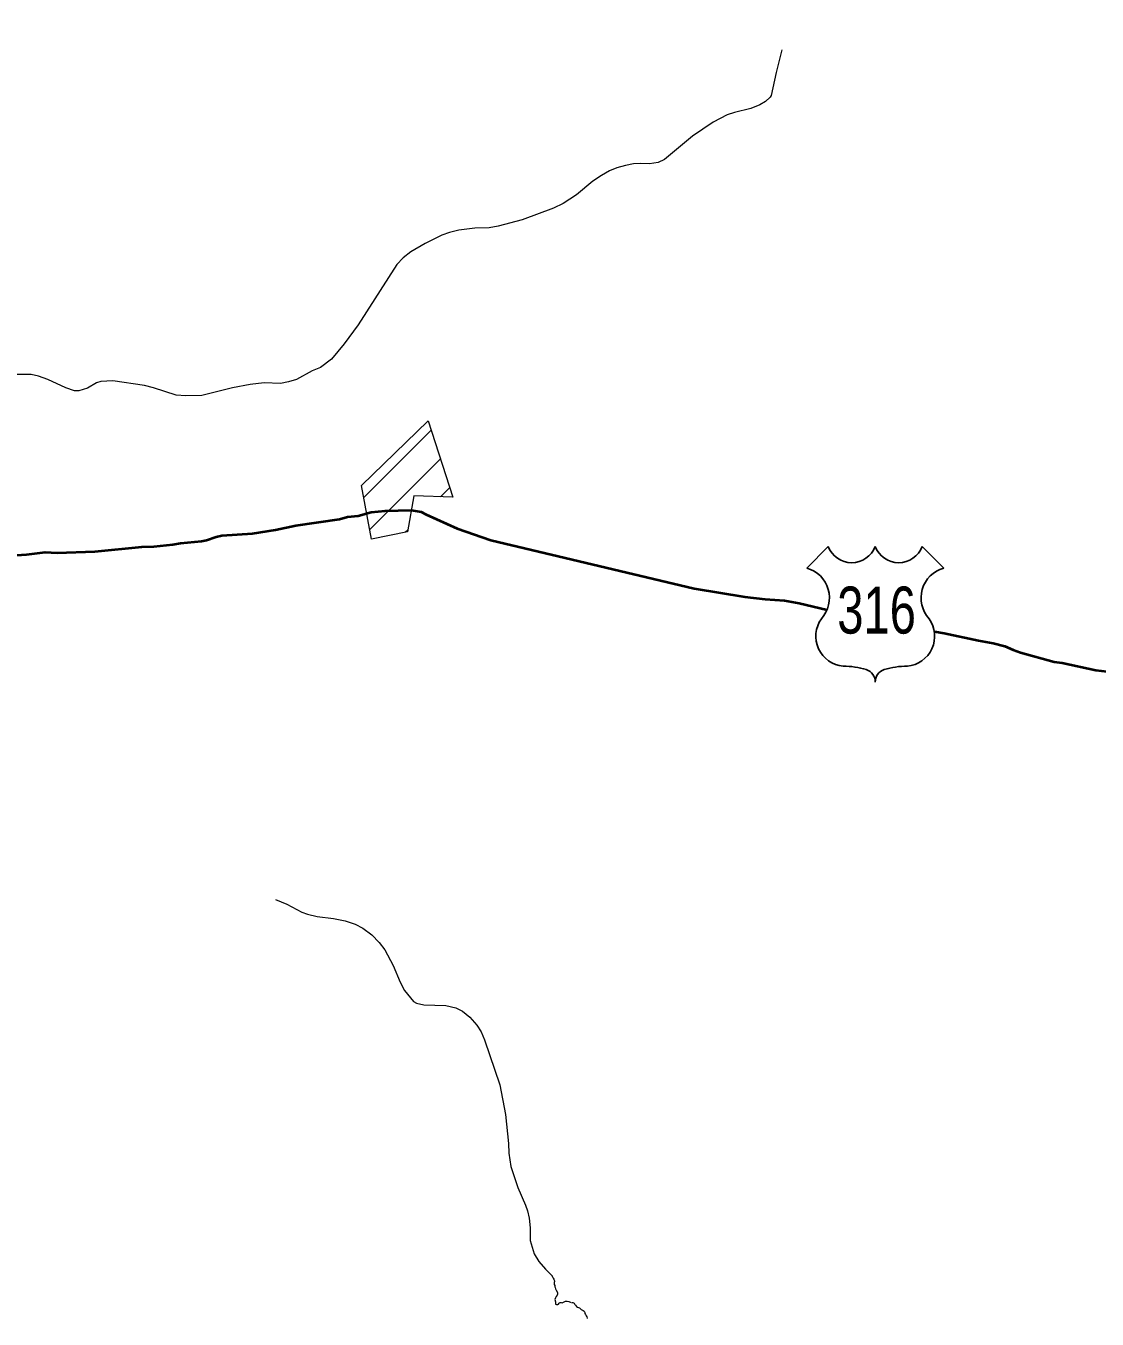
# Model space of a CAD drawing. Extents: x -1643653 to 4543381, y 1624270 to 13878484.
# Drawn here: x 612033 to 613629, y 8911161 to 8913088 of the extents above; entities that cross this region are included whole.
import ezdxf
from ezdxf.enums import TextEntityAlignment as Align

# ---------------------------------------------------------------- set-up
doc = ezdxf.new("R2010")
doc.units = 0
doc.header["$LTSCALE"] = 160
doc.layers.add('6', color=7, linetype='Continuous', lineweight=13)
doc.layers.add('60', color=7, linetype='Continuous', lineweight=13)

msp = doc.modelspace()

# ---------------------------------------------------------------- linework, layer by layer
at = {"layer": '6'}
for p, q in [((612536.6, 8912385.5), (612637.1, 8912486)), ((612545.6, 8912337.9), (612650.9, 8912443.2)), ((612651.1, 8912386.8), (612664.7, 8912400.5)), ((612598.1, 8912333.9), (612602.5, 8912338.2))]:
    msp.add_line(p, q, dxfattribs=at)
at = {"layer": '6', "lineweight": 25}
for p, q in [((613196.5, 8912280.5), (613228.5, 8912312.5)), ((613368.3, 8912312.5), (613400.3, 8912280.5))]:
    msp.add_line(p, q, dxfattribs=at)
at = {"layer": '6'}
for points in [[(613159.1, 8913052.5), (613150.7, 8913018.9), (613143.3, 8912984.7), (613141.8, 8912982.2), (613135, 8912975.7), (613126.6, 8912970.5), (613113.2, 8912965.1), (613088.7, 8912959.4), (613077.6, 8912955.9), (613056.8, 8912945.1), (613026.4, 8912924.2), (612984.3, 8912889.5), (612975.3, 8912885), (612962, 8912882.7), (612949.3, 8912883.3), (612938.2, 8912882.9), (612926.3, 8912880.4), (612913.6, 8912876.7), (612902.5, 8912872.2), (612890.6, 8912865.5), (612878, 8912856.9), (612853.6, 8912836.8), (612833.4, 8912823.5), (612819.3, 8912816.9), (612772.4, 8912799.4), (612736.7, 8912790.1), (612723.2, 8912787.6), (612701.8, 8912787.2), (612678, 8912783.9), (612664.5, 8912780.4), (612652.7, 8912776.3), (612628.1, 8912764), (612606.6, 8912751.9), (612595.2, 8912743), (612585.7, 8912732.6), (612528.2, 8912642.8), (612507.4, 8912614.5), (612488.7, 8912591.9), (612472.2, 8912579.6), (612459.6, 8912574.3), (612436.4, 8912561.7), (612424.6, 8912558.2), (612412.7, 8912555.7), (612388.1, 8912556.3), (612367.4, 8912554.2), (612341.2, 8912549.2), (612295.2, 8912537.7), (612271.4, 8912536.9), (612257.2, 8912538.1), (612223.7, 8912549.1), (612210.3, 8912552.6), (612162.7, 8912559.7), (612144.9, 8912558.7), (612138.8, 8912556.3), (612125.4, 8912548.8), (612112.3, 8912544.7), (612106, 8912544.6), (612092.8, 8912549.1), (612065.9, 8912561.3), (612052.4, 8912566.6), (612041.2, 8912568.8), (612020.6, 8912568.7)], [(612405.4, 8911786.9), (612421.9, 8911779.7), (612444.2, 8911767.9), (612452.9, 8911764.7), (612467, 8911761.3), (612491.4, 8911758.4), (612508.9, 8911754.9), (612524, 8911749.8), (612535, 8911743.9), (612548.6, 8911733.8), (612559.7, 8911722.7), (612568.1, 8911711.9), (612580.6, 8911688.2), (612590.9, 8911663.6), (612597.2, 8911651.2), (612610.8, 8911634.7), (612615.1, 8911632.4), (612626.2, 8911629.9), (612658.6, 8911628.8), (612673.5, 8911625.1), (612683.9, 8911620.1), (612694.8, 8911611.3), (612705, 8911599.6), (612711.5, 8911589.3), (612716.3, 8911577.6), (612739.5, 8911510.5), (612747.7, 8911466.3), (612752.2, 8911422.9), (612752.6, 8911408.8), (612755.4, 8911389), (612765.9, 8911357.3), (612777.4, 8911331.4), (612780.4, 8911322.6), (612782.9, 8911311.6), (612784.4, 8911297.5), (612784.2, 8911278.4), (612790.5, 8911258.6), (612797.4, 8911247.3), (612807.2, 8911235.8), (612817.1, 8911225.9)], [(612817.1, 8911225.9), (612817.4, 8911225), (612818, 8911223.9), (612818.6, 8911222.4), (612819.6, 8911220.8), (612820.4, 8911219.5), (612820.6, 8911218.7), (612820.6, 8911217.4), (612820.3, 8911215.9), (612820.2, 8911213.9), (612820.4, 8911213), (612821.1, 8911211.6), (612821.3, 8911210.5), (612821, 8911209.4)], [(612821, 8911209.4), (612821.6, 8911208.3), (612822.4, 8911206.7), (612823.2, 8911204.4), (612824.9, 8911200.9), (612825.3, 8911199.8), (612825.2, 8911198.6), (612824.6, 8911197.1), (612823.1, 8911195.1), (612822, 8911193.1), (612821.4, 8911190.8), (612822.3, 8911187), (612822.3, 8911184.5), (612822.3, 8911183.5)], [(612822.3, 8911183.6), (612823.9, 8911183.1), (612824.8, 8911183), (612825.5, 8911183.1), (612826.4, 8911183.6), (612827.5, 8911185), (612828.1, 8911185.7), (612829, 8911186), (612830.5, 8911186), (612832.3, 8911185.9), (612834.3, 8911186.6), (612835.2, 8911187), (612837.1, 8911188), (612838.2, 8911188.2), (612839.3, 8911188), (612841.9, 8911187.6), (612843.1, 8911187.2), (612844.3, 8911186.8), (612845.2, 8911186.6)], [(612845.8, 8911186.4), (612847.8, 8911186.2), (612848.8, 8911185.9), (612850.1, 8911185.3), (612851.1, 8911183.4), (612851.8, 8911182.1), (612853.2, 8911180.4), (612854.8, 8911179.4), (612856.6, 8911178.8), (612858, 8911178), (612859.3, 8911176.8), (612860.2, 8911175.8), (612861.6, 8911175.2), (612863.6, 8911174.4), (612864.9, 8911173.1), (612865.7, 8911171.2), (612866, 8911169.8), (612866.6, 8911168.1), (612868, 8911166.1), (612868.8, 8911164.7), (612869.4, 8911162.7), (612869.5, 8911162.2)]]:
    msp.add_lwpolyline(points, dxfattribs=at)
msp.add_lwpolyline([(612533.2, 8912403.4), (612632.5, 8912500.1), (612669.3, 8912386.3), (612611.2, 8912388.1), (612601.8, 8912334.6), (612548.3, 8912323.5)], close=True, dxfattribs=at)
at = {"layer": '6', "lineweight": 40}
for points in [[(611998, 8912298.2), (612034.4, 8912300.8), (612062.1, 8912304), (612080.2, 8912303.3), (612136.2, 8912305), (612205.9, 8912312.1), (612224, 8912312.5), (612252.3, 8912315.6), (612263.9, 8912317.7), (612294.8, 8912320.4), (612302.5, 8912322), (612316.8, 8912326.8), (612325.2, 8912328.8), (612370.8, 8912332), (612405.4, 8912337.7), (612435.2, 8912344), (612500.6, 8912353.4), (612512.3, 8912356.6), (612528.3, 8912358.5), (612547.5, 8912363.6), (612568.3, 8912366), (612607.2, 8912366.8), (612622, 8912364.3), (612629.4, 8912360.3), (612675.8, 8912339.5), (612726, 8912322.1), (613028.9, 8912249.9)], [(613028.9, 8912249.9), (613104.3, 8912237.7), (613134.5, 8912234.3), (613163.2, 8912232.2), (613185.3, 8912228.2), (613226.8, 8912218.5)], [(613386.4, 8912186.2), (613401.2, 8912183.6), (613452.1, 8912172.7), (613474.2, 8912168.8), (613491.2, 8912163.9), (613503.7, 8912158.5), (613514.7, 8912154.8), (613564.8, 8912141), (613576.6, 8912139.3), (613626.7, 8912128.5), (613660.6, 8912124.5)]]:
    msp.add_lwpolyline(points, dxfattribs=at)
at = {"layer": '6', "lineweight": 25}
for centre, radius, start, end in [((613263.4, 8912325.9), 37.4, 200.9593, 339.0407), ((613333.4, 8912325.9), 37.4, 200.9593, 339.0407), ((613184.1, 8912236.1), 46.1, 317.5721, 74.3689), ((613412.7, 8912236.1), 46.1, 105.6277, 222.4279), ((613254.8, 8912179.1), 44.9, 144.7373, 264.6578), ((613342, 8912179.1), 44.9, 275.3422, 35.2627), ((613250.4, 8912016.4), 118, 72.8937, 89.9006), ((613279.5, 8912111.1), 18.9, 357.6934, 72.9296), ((613317.3, 8912111.1), 18.9, 107.0704, 182.3065), ((613346.4, 8912016.4), 118, 90.0994, 107.1063)]:
    msp.add_arc(centre, radius, start, end, dxfattribs=at)
at = {"layer": '60', "lineweight": 25}
msp.add_spline([(814781, 9009175.5), (814787.2, 9009173.4), (814796.9, 9009173.4), (814799.4, 9009172.4), (814805.1, 9009174.5), (814805.6, 9009176.5), (814811.7, 9009179.5), (814811.7, 9009179.5), (814801.5, 9009181), (814790.7, 9009181.5), (814784.1, 9009183.1), (814777.4, 9009185.1), (814778.4, 9009175.5)], degree=3, dxfattribs=at)

# ---------------------------------------------------------------- texts
at = {"layer": '6', "width": 0.75}
msp.add_text('316', height=70, dxfattribs=at).set_placement((613300.4, 8912182.9), align=Align.CENTER)

doc.saveas('drawing.dxf')
